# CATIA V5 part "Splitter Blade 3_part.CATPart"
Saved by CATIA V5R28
Part number: Splitter Blade 3_part
Definition: design
Nomenclature: Splitter Blade 3_part
Source: Unknown
Bounding box of the stored display mesh (mm): x 2.481 to 9.986, y -1.572 to 4.309, z 4.237 to 7.742
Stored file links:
  D:\paraturbo-cad\STEP\Turbocompressor_for_Christophe\Splitter Blade 3_part.CATPart
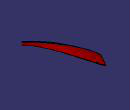
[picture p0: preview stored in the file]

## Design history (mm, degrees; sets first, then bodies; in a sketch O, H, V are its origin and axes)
Body1 "MANIFOLD_SOLID_BREP #64532" (main body)
  Solid1: solid without history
